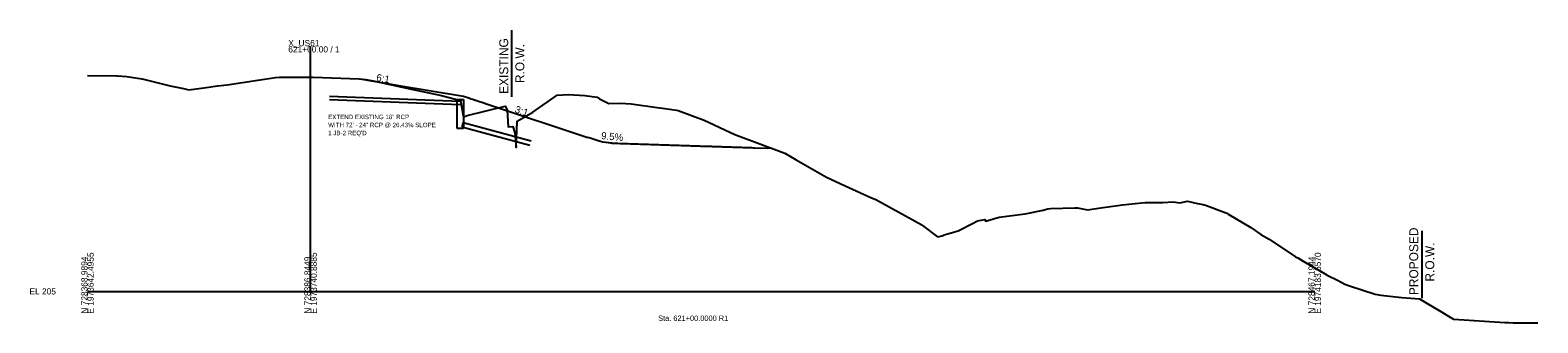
# Model space of a CAD drawing. Extents: x -26 to 1629, y -25 to 9635.
# Drawn here: x -26 to 650, y 2486 to 2617 of the extents above; entities that cross this region are included whole.
import ezdxf

# ---------------------------------------------------------------- set-up
doc = ezdxf.new("R2010")
doc.units = 0
for name, color, linetype in [('Default', 7, 'Continuous'), ('Draft_XS_Grid', 7, 'Continuous'), ('Draft_XS_Text', 7, 'Continuous'), ('DTM CONTOURS_MAJOR', 7, 'Continuous'), ('DTM_X_GROUND', 7, 'Continuous'), ('XS_CELL', 7, 'Continuous'), ('XS_P_DRAINAGE', 7, 'Continuous'), ('XS_P_GROUND', 7, 'Continuous'), ('XS_P_ROW', 7, 'Continuous'), ('XS_P_TX_FS_BS', 7, 'Continuous'), ('XS_X_DRAINAGE', 7, 'Continuous'), ('XS_X_ROW', 7, 'Continuous')]:
    doc.layers.add(name, color=color, linetype=linetype)

msp = doc.modelspace()

# ---------------------------------------------------------------- linework, layer by layer
at = {"layer": 'DTM_X_GROUND'}
msp.add_lwpolyline([(0, 2596.91), (13.06, 2596.71), (13.37, 2596.7), (13.39, 2596.7), (17.6, 2596.35), (24.34, 2595.41), (24.5, 2595.38), (37.05, 2592.18), (43.07, 2590.96), (45.42, 2590.49), (53.21, 2591.51), (58.33, 2592.24), (62.62, 2592.66), (76.36, 2594.78), (84.29, 2596), (86.08, 2596.09), (87.22, 2596.15), (90.97, 2596.15), (101.12, 2596.13), (121.79, 2595.38), (121.83, 2595.38), (121.83, 2595.38), (124.72, 2595.06), (127.98, 2594.42), (145.87, 2590.57), (150.83, 2589.54), (158.65, 2587.83), (167.16, 2585.66), (168.44, 2578.74), (168.5, 2578.54), (168.69, 2578.3), (170.17, 2578.86), (187.22, 2583.17), (188.04, 2581.41), (188.57, 2573.84), (190.62, 2573.93), (191.58, 2571.12), (192.06, 2564.55), (192.55, 2576.42), (199.66, 2580.48), (210.47, 2588.04), (215.5, 2588.33), (222.83, 2587.83), (228.46, 2587.1), (229.47, 2586.33), (233.62, 2584.3), (238.69, 2584.38), (243.72, 2584.08), (256.39, 2582.37), (257.71, 2582.2), (263.95, 2581.32), (264.65, 2581.2), (276.41, 2576.81), (290.1, 2570.45), (312.48, 2562), (317.61, 2558.99), (331.21, 2551.2), (339.63, 2547.32), (351.39, 2542), (353.37, 2541.29), (356.29, 2539.63), (373.96, 2529.79), (374.19, 2529.52), (380.89, 2524.47), (381.01, 2524.43), (382.98, 2524.92), (383.99, 2525.36), (390.22, 2527.16), (396.64, 2530.52), (398.94, 2531.68), (402.23, 2532.23), (402.66, 2531.52), (402.67, 2531.51), (403.52, 2531.8), (408.52, 2533.28), (413.27, 2533.87), (420.22, 2534.73), (428.24, 2536.38), (428.71, 2536.53), (430.32, 2537.02), (431.62, 2537.18), (442.45, 2537.48), (443.72, 2537.42), (448.22, 2536.65), (454.08, 2537.46), (463.85, 2538.85), (471, 2539.59), (473.97, 2539.86), (481.94, 2539.89), (486.5, 2540.15), (489.5, 2539.77), (492.93, 2540.51), (497.54, 2539.5), (500, 2538.94), (501.46, 2538.47), (510.63, 2535.02), (511.12, 2534.72), (511.19, 2534.66), (511.48, 2534.52), (521.43, 2528.64), (521.86, 2528.38), (525.88, 2525.54), (529.56, 2523.38), (541.34, 2515.57), (541.74, 2515.32), (542.39, 2514.98), (544.83, 2513.55), (554.38, 2507.95), (555.65, 2507.24), (560.49, 2504.81), (563.57, 2503.28), (565.65, 2502.44), (577.02, 2498.69), (579.6, 2498.28), (589.03, 2497.26), (597.03, 2496.64), (600.68, 2494.45), (605.07, 2491.82), (612.2, 2487.56), (612.3, 2487.49), (635.23, 2486.07), (636.76, 2485.98), (637.07, 2485.96), (638.97, 2485.88), (639.78, 2485.86), (650, 2485.86)], dxfattribs=at)
at = {"layer": 'XS_CELL'}
for p, q in [((100, 2500), (100, 2610)), ((0, 2500), (100, 2500)), ((100, 2500), (550, 2500))]:
    msp.add_line(p, q, dxfattribs=at)
at = {"layer": 'XS_P_DRAINAGE'}
for p, q in [((165.5, 2586.16), (165.5, 2573.29)), ((165.5, 2586.16), (168.5, 2586.16)), ((168.5, 2586.16), (168.5, 2573.29)), ((168.32, 2575.73), (167.81, 2573.8)), ((168.32, 2575.73), (198.78, 2567.62)), ((165.5, 2573.29), (168.5, 2573.29)), ((167.81, 2573.8), (198.27, 2565.68))]:
    msp.add_line(p, q, dxfattribs=at)
at = {"layer": 'XS_P_GROUND'}
for points in [[(122, 2595.36), (134.24, 2593.32), (138.62, 2592.59), (168.5, 2587.61)], [(168.5, 2587.61), (170.52, 2586.94), (170.83, 2586.83), (170.93, 2586.8), (171.93, 2586.46), (171.96, 2586.46), (172.64, 2586.23), (172.66, 2586.22), (173.81, 2585.84), (173.84, 2585.83), (174.42, 2585.63), (174.44, 2585.63), (175.6, 2585.24), (175.64, 2585.23), (176.22, 2585.03), (176.24, 2585.03), (178.03, 2584.43), (178.08, 2584.41), (178.68, 2584.21), (178.7, 2584.21), (179.31, 2584), (179.33, 2584), (224.3, 2569.01)], [(229.81, 2567.2), (225.25, 2568.78), (224.3, 2569.01), (224.3, 2569.01), (224.3, 2569.01), (224.3, 2569.01)], [(307.06, 2564.05), (298.89, 2564.31), (298.53, 2564.32), (297.75, 2564.35), (297.38, 2564.36), (296.62, 2564.39), (296.23, 2564.4), (295.49, 2564.42), (295.08, 2564.44), (294.35, 2564.46), (293.93, 2564.47), (293.22, 2564.5), (292.78, 2564.51), (292.09, 2564.53), (291.63, 2564.55), (290.95, 2564.57), (290.48, 2564.58), (289.82, 2564.61), (289.33, 2564.62), (288.69, 2564.64), (288.18, 2564.66), (287.55, 2564.68), (287.03, 2564.7), (286.42, 2564.72), (285.88, 2564.73), (285.29, 2564.75), (284.73, 2564.77), (284.15, 2564.79), (283.58, 2564.81), (283.02, 2564.83), (282.43, 2564.85), (281.89, 2564.86), (281.28, 2564.88), (280.75, 2564.9), (280.13, 2564.92), (279.62, 2564.94), (278.98, 2564.96), (278.49, 2564.97), (277.84, 2564.99), (277.35, 2565.01), (276.69, 2565.03), (276.22, 2565.05), (275.54, 2565.07), (275.09, 2565.08), (274.39, 2565.11), (273.95, 2565.12), (273.25, 2565.14), (272.82, 2565.16), (272.1, 2565.18), (271.69, 2565.19), (270.95, 2565.22), (270.55, 2565.23), (269.8, 2565.25), (269.42, 2565.27), (268.65, 2565.29), (268.29, 2565.3), (267.5, 2565.33), (267.15, 2565.34), (266.36, 2565.37), (266.02, 2565.38), (265.21, 2565.4), (264.89, 2565.41), (264.06, 2565.44), (263.75, 2565.45), (262.91, 2565.48), (262.62, 2565.49), (261.77, 2565.51), (261.49, 2565.52), (260.62, 2565.55), (260.35, 2565.56), (259.47, 2565.59), (259.22, 2565.6), (258.32, 2565.63), (258.09, 2565.63), (257.17, 2565.66), (256.95, 2565.67), (256.02, 2565.7), (255.82, 2565.71), (254.88, 2565.74), (254.69, 2565.74), (253.73, 2565.77), (253.55, 2565.78), (252.58, 2565.81), (252.42, 2565.82), (251.43, 2565.85), (251.29, 2565.85), (250.28, 2565.89), (250.15, 2565.89), (249.14, 2565.92), (249.02, 2565.93), (247.99, 2565.96), (247.89, 2565.96), (246.84, 2566), (246.75, 2566), (246.67, 2566), (245.62, 2566.04), (245.55, 2566.04), (244.49, 2566.07), (244.43, 2566.07), (243.35, 2566.11), (243.31, 2566.11), (242.22, 2566.15), (242.19, 2566.15), (241.09, 2566.18), (240.11, 2566.21), (239.95, 2566.22), (239.93, 2566.22), (238.82, 2566.26), (238.66, 2566.26), (237.69, 2566.29), (237.4, 2566.3), (236.55, 2566.33), (236.13, 2566.34), (235.42, 2566.37), (235.21, 2566.38), (235.07, 2566.43), (234.78, 2566.47), (234.49, 2566.51), (233.79, 2566.61), (233.33, 2566.68), (232.49, 2566.8), (232.18, 2566.85), (231.18, 2567), (231.02, 2567.02), (229.88, 2567.19), (229.87, 2567.19), (229.81, 2567.2)]]:
    msp.add_lwpolyline(points, dxfattribs=at)
at = {"layer": 'XS_P_ROW'}
msp.add_line((598, 2527.2), (598, 2496.88), dxfattribs=at)
at = {"layer": 'XS_X_DRAINAGE'}
for p, q in [((108.39, 2586.11), (167, 2583.89)), ((108.45, 2587.61), (167.06, 2585.39))]:
    msp.add_line(p, q, dxfattribs=at)
at = {"layer": 'XS_X_ROW'}
msp.add_line((190, 2617.23), (190, 2587.34), dxfattribs=at)

# ---------------------------------------------------------------- texts
at = {"layer": 'Default'}
msp.add_text('X', height=0.12, dxfattribs=at).set_placement((207.51, 2570.51))
at = {"layer": 'Draft_XS_Grid'}
msp.add_text('-', height=0.0001, dxfattribs=at).set_placement((0, 2500))
at = {"layer": 'Draft_XS_Text'}
msp.add_text('Sta. 621+00.0000 R1', height=2.4, dxfattribs=at).set_placement((255.75, 2486.75))
at = {"layer": 'DTM CONTOURS_MAJOR'}
for p in [(121.96, 2595.3), (141.96, 2591.96), (141.96, 2591.96), (141.96, 2591.96), (192.46, 2575.13), (192.51, 2576.32), (201.51, 2572.11), (217.82, 2570.87)]:
    msp.add_text('X', height=0.12, dxfattribs=at).set_placement(p)
at = {"layer": 'XS_CELL'}
for s, p in [('X_US61', (90, 2610)), ('621+00.00 / 1', (90, 2607.2)), ('EL 205', (-26, 2498.6))]:
    msp.add_text(s, height=2.8, dxfattribs=at).set_placement(p)
for s, p in [('N 728368.9894', (0, 2490)), ('E 1973642.4955', (2.8, 2490)), ('N 728386.8449', (100, 2490)), ('E 1973740.8885', (102.8, 2490)), ('N 728467.1944', (550, 2490)), ('E 1974183.6570', (552.8, 2490))]:
    msp.add_text(s, height=2.8, rotation=90, dxfattribs=at).set_placement(p)
at = {"layer": 'XS_P_DRAINAGE'}
for s, p in [('WITH 72\' - 24" RCP @ 26.43% SLOPE', (107.88, 2573.68)), ('EXTEND EXISTING 18" RCP', (107.88, 2577.28)), ("1 JB-2 REQ'D", (107.88, 2570.08))]:
    msp.add_text(s, height=2, dxfattribs=at).set_placement(p)
at = {"layer": 'XS_P_ROW'}
for s, p in [('PROPOSED', (596.37, 2498.33)), ('R.O.W.', (603.57, 2504.4))]:
    msp.add_text(s, height=4, rotation=90, dxfattribs=at).set_placement(p)
at = {"layer": 'XS_P_TX_FS_BS'}
for s, rotation, p in [('6:1', 350.53766, (129.26, 2594.45)), ('3:1', 341.56507, (191.23, 2580.35)), ('9.5%', 354.55411, (230.09, 2568.33))]:
    msp.add_text(s, height=3.24, rotation=rotation, dxfattribs=at).set_placement(p)
at = {"layer": 'XS_X_ROW'}
for s, p in [('EXISTING', (188.56, 2588.62)), ('R.O.W.', (195.76, 2593.46))]:
    msp.add_text(s, height=4, rotation=90, dxfattribs=at).set_placement(p)

doc.saveas('drawing.dxf')
